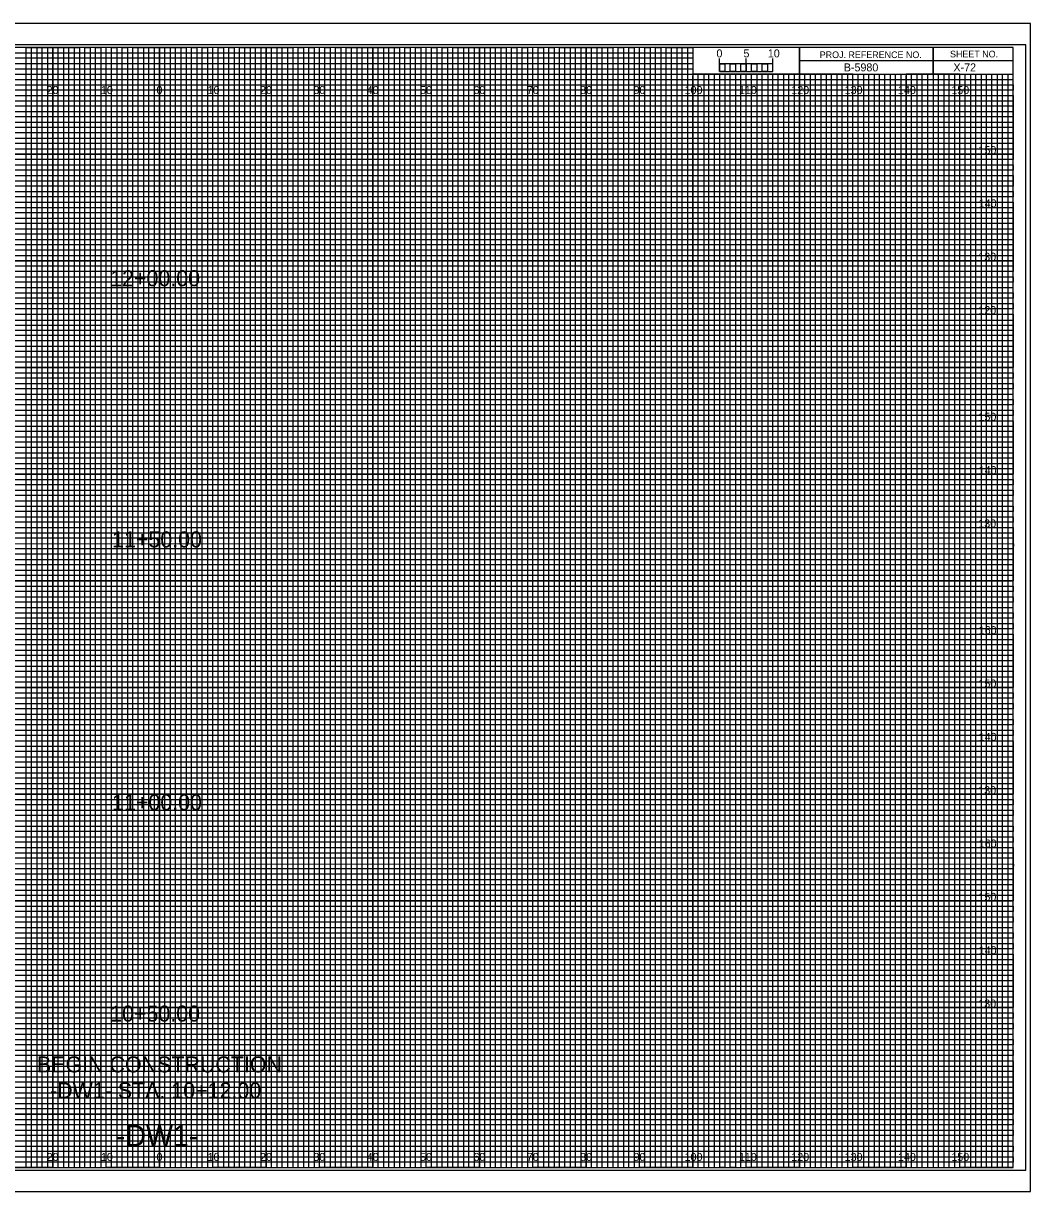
# Model space of a CAD drawing. Extents: x -13 to 323, y -5 to 434.
# Drawn here: x 134.5 to 323.3, y -4.5 to 214.5 of the extents above; entities that cross this region are included whole.
import ezdxf

# ---------------------------------------------------------------- set-up
doc = ezdxf.new("R2010")
doc.units = 0
for name, color, linetype in [('Exist Cross Section Cell', 7, 'Continuous'), ('Exist XS Center Line Elevation Label', 7, 'Continuous'), ('Exist XS Ground Line', 7, 'Continuous'), ('Prop CMT Pvmt Course 1', 7, 'Continuous'), ('Prop CMT Pvmt Course 1 Wedge', 7, 'Continuous'), ('Prop CMT Pvmt Course 2', 7, 'Continuous'), ('Prop CMT Pvmt Course 3', 7, 'Continuous'), ('Prop CMT Pvmt Surface', 7, 'Continuous'), ('Prop CMT Pvmt Surface Shoulder', 7, 'Continuous'), ('Prop CMT Shld Paved Course 1', 7, 'Continuous'), ('Prop CMT Shld Paved Course 2', 7, 'Continuous'), ('Prop CMT Shld Paved Course 3', 7, 'Continuous'), ('Prop CMT Slope Grass', 7, 'Continuous'), ('Prop CMT Subgrade Earthwork', 7, 'Continuous'), ('Prop XS Ditch Standard Text', 7, 'Continuous'), ('Prop XS SE Text', 7, 'Continuous'), ('Prop XS Side Slope Text', 7, 'Continuous')]:
    doc.layers.add(name, color=color, linetype=linetype)

msp = doc.modelspace()

# ---------------------------------------------------------------- linework, layer by layer
at = {"layer": 'Exist XS Center Line Elevation Label'}
for points in [[(125, 0), (135, 0), (135, 210), (145, 210), (145, 0), (155, 0), (155, 210), (165, 210), (165, 0), (175, 0), (175, 210), (185, 210), (185, 0), (195, 0), (195, 210), (205, 210), (205, 0), (215, 0), (215, 210), (225, 210), (225, 0), (235, 0), (235, 210), (245, 210), (245, 0), (255, 0), (255, 210), (259.93, 210), (260, 210), (260, 205), (264.99, 205), (264.99, 0), (275, 0), (275, 205), (285, 205), (285, 0), (295, 0), (295, 205), (305, 205), (305, 0), (315, 0), (315, 205)], [(0, 205), (275, 205)], [(0, 185), (320, 185), (320, 195), (0, 195)], [(0, 165), (320, 165), (320, 175), (0, 175)], [(0, 145), (320, 145), (320, 155), (0, 155)], [(0, 125), (320, 125), (320, 135), (0, 135)], [(0, 105), (320, 105), (320, 115), (0, 115)], [(0, 85), (320, 85), (320, 95), (0, 95)], [(0, 65), (320, 65), (320, 75), (0, 75)], [(0, 45), (320, 45), (320, 55), (0, 55)], [(0, 25), (320, 25), (320, 35), (0, 35)], [(0, 5), (320, 5), (320, 15), (0, 15)]]:
    msp.add_lwpolyline(points, dxfattribs=at)
at = {"layer": 'Exist XS Ground Line'}
for p, q in [((150, 210), (140, 210)), ((140, 210), (140, 0)), ((150, 0), (150, 210)), ((170, 210), (160, 210)), ((160, 210), (160, 0)), ((170, 0), (170, 210)), ((190, 210), (180, 210)), ((180, 210), (180, 0)), ((190, 0), (190, 210)), ((210, 210), (200, 210)), ((200, 210), (200, 0)), ((210, 0), (210, 210)), ((230, 210), (220, 210)), ((220, 210), (220, 0)), ((230, 0), (230, 210)), ((250, 210), (240, 210)), ((240, 210), (240, 0)), ((250, 0), (250, 210)), ((260, 210), (260, 0)), ((270, 0), (270, 205)), ((290, 205), (280, 205)), ((280, 205), (280, 0)), ((290, 0), (290, 205)), ((310, 205), (300, 205)), ((300, 205), (300, 0)), ((310, 0), (310, 205)), ((140, 0), (130, 0)), ((160, 0), (150, 0)), ((180, 0), (170, 0)), ((200, 0), (190, 0)), ((220, 0), (210, 0)), ((240, 0), (230, 0)), ((260, 0), (250, 0)), ((280, 0), (270, 0)), ((300, 0), (290, 0)), ((320, 0), (310, 0)), ((320, 0), (320, 0))]:
    msp.add_line(p, q, dxfattribs=at)
for points in [[(0, 200), (320, 200), (320, 190), (0, 190)], [(0, 180), (320, 180), (320, 170), (0, 170)], [(0, 160), (320, 160), (320, 150), (0, 150)], [(0, 140), (320, 140), (320, 130), (0, 130)], [(0, 120), (320, 120), (320, 110), (0, 110)], [(0, 100), (320, 100), (320, 90), (0, 90)], [(0, 80), (320, 80), (320, 70), (0, 70)], [(0, 60), (320, 60), (320, 50), (0, 50)], [(0, 40), (320, 40), (320, 30), (0, 30)], [(0, 20), (320, 20), (320, 10), (0, 10)]]:
    msp.add_lwpolyline(points, dxfattribs=at)
at = {"layer": 'Prop CMT Pvmt Course 2'}
for p, q in [((265, 205.49), (265, 207.9)), ((265, 206.9), (265, 207.9)), ((270, 205.49), (270, 207.9)), ((275, 205.49), (275, 207.9)), ((275, 206.9), (275, 207.9))]:
    msp.add_line(p, q, dxfattribs=at)
for points in [[(275, 206.9), (265, 206.9), (265, 205.49), (275, 205.49)], [(265, 206.9), (266, 206.9), (266, 205.49), (265, 205.49)], [(267, 206.9), (268, 206.9), (268, 205.49), (267, 205.49)], [(269, 206.9), (270, 206.9), (270, 205.49), (269, 205.49)], [(271, 206.9), (272, 206.9), (272, 205.49), (271, 205.49)], [(273, 206.9), (274, 206.9), (274, 205.49), (273, 205.49)]]:
    msp.add_lwpolyline(points, close=True, dxfattribs=at)
at = {"layer": 'Prop CMT Pvmt Course 3'}
msp.add_lwpolyline([(-13.4, -4.5), (323.3, -4.5), (323.3, 214.5), (-13.4, 214.5)], close=True, dxfattribs=at)
at = {"layer": 'Prop CMT Pvmt Surface'}
for p, q in [((140, 0), (140, 210)), ((150, 0), (150, 210)), ((160, 0), (160, 210)), ((170, 0), (170, 210)), ((180, 0), (180, 210)), ((190, 0), (190, 210)), ((200, 0), (200, 210)), ((210, 0), (210, 210)), ((220, 0), (220, 210)), ((230, 0), (230, 210)), ((240, 0), (240, 210)), ((250, 0), (250, 210)), ((260, 0), (260, 204.69)), ((270, 0), (270, 204.69)), ((280, 0), (280, 204.69)), ((290, 0), (290, 204.69)), ((300, 0), (300, 204.69)), ((310, 0), (310, 204.69)), ((0, 200), (320, 200)), ((0, 190), (320, 190)), ((0, 180), (320, 180)), ((0, 170), (320, 170)), ((0, 160), (320, 160)), ((0, 150), (320, 150)), ((0, 140), (320, 140)), ((0, 130), (320, 130)), ((0, 120), (320, 120)), ((0, 110), (320, 110)), ((0, 100), (320, 100)), ((0, 90), (320, 90)), ((0, 80), (320, 80)), ((0, 70), (320, 70)), ((0, 60), (320, 60)), ((0, 50), (320, 50)), ((0, 40), (320, 40)), ((0, 30), (320, 30)), ((0, 20), (320, 20)), ((0, 10), (320, 10))]:
    msp.add_line(p, q, dxfattribs=at)
at = {"layer": 'Prop CMT Pvmt Surface Shoulder'}
for p, q in [((323.3, 214.5), (-13.4, 214.5)), ((-13.4, -4.5), (323.3, -4.5))]:
    msp.add_line(p, q, dxfattribs=at)
at = {"layer": 'Prop CMT Shld Paved Course 1'}
for p, q in [((0, 209), (260, 209)), ((260, 209), (260, 207.98)), ((260, 207.98), (0, 207.98)), ((0, 207), (260, 207)), ((260, 205.89), (0, 205.89)), ((260, 207), (260, 205.89)), ((0, 204), (320, 204))]:
    msp.add_line(p, q, dxfattribs=at)
for points in [[(0, 203), (270, 203), (320, 203), (320, 202), (0, 202)], [(0, 201), (320, 201), (320, 199), (0, 199)], [(0, 198), (320, 198), (320, 197), (0, 196.98)], [(0, 196), (320, 196), (320, 194), (0, 194)], [(0, 193), (320, 193), (320, 192), (0, 192)], [(0, 191), (320, 191), (320, 189), (0, 189)], [(0, 188), (320, 188), (320, 187), (0, 187)], [(0, 186), (320, 186), (320, 184), (0, 184)], [(0, 183), (320, 183), (320, 182), (0, 182)], [(0, 181), (320, 181), (320, 179), (0, 179)], [(0, 178), (320, 178), (320, 177), (0, 177)], [(0, 176), (320, 176), (320, 173.95), (320, 173), (320, 172), (0, 172)], [(0, 174), (320, 174), (320, 173), (0, 173)], [(0, 171), (320, 171), (320, 169), (0, 169.03)], [(0, 169.03), (320, 169), (320, 168), (0, 168)], [(0, 167), (320, 167), (320, 166), (0, 166)], [(0, 164), (320, 164), (320, 163), (0, 163)], [(0, 162), (320, 162), (320, 161), (0, 161)], [(-0.07, 158.89), (320, 158.89), (320, 157.88), (-0.07, 157.88)], [(0, 157), (320, 157), (320, 156), (0, 156)], [(0, 154), (320, 154), (320, 153), (0, 153)], [(0, 152), (320, 152), (320, 151), (0, 151)], [(0, 149), (320, 149), (320, 148), (0, 148)], [(0, 147), (320, 147), (320, 146), (0, 146)], [(0, 144), (320, 144), (320, 143), (0, 143)], [(0, 142), (320, 142), (320, 141), (0, 141)], [(0, 139), (320, 139), (319.99, 137.98), (0, 138)], [(0, 137), (320, 137), (320, 136), (0, 136)], [(0, 134), (320, 134), (320, 133), (0, 133)], [(0, 132), (320, 132), (320, 131), (0, 131)], [(0, 129), (320, 129), (320, 128), (0, 128)], [(0, 127), (320, 127), (320, 126), (0, 126)], [(0, 124), (320, 124), (320, 123), (0, 123)], [(0, 122), (320, 122), (320, 121), (0, 121)], [(0, 119), (320, 119), (320, 118), (0, 118)], [(0, 116.99), (320.07, 116.91), (320, 116), (0, 116)], [(0, 114), (320, 114), (320, 113), (0, 113)], [(0, 112), (320, 112), (320, 111), (0, 111)], [(0, 109), (320, 109), (320, 108), (0, 108)], [(0, 107), (320, 107), (320, 106), (0, 106)], [(0, 104), (320, 104), (320, 103), (0, 103)], [(0, 102), (320, 102), (320, 101), (0, 101)], [(0, 99), (320, 99), (320, 98), (0, 98)], [(0, 97), (320, 97), (320, 96), (0, 96)], [(0, 94), (320, 94), (320, 93), (0, 93)], [(0, 92), (320, 92), (320, 91), (0, 91)], [(0, 89), (320, 89), (320, 88), (0, 88)], [(0, 87), (320, 87), (320, 86), (0, 86)], [(0, 84), (320, 84), (320, 83), (0, 83)], [(0, 82), (320, 82), (320, 81), (0, 81)], [(0, 79), (320, 79), (319.99, 77.98), (0, 78)], [(0, 77), (320, 77), (320, 76), (0, 76)], [(0, 74), (320, 74), (320, 73), (0, 73)], [(0, 72), (320, 72), (320, 71), (0, 71)], [(0, 69), (320, 69), (320, 68), (0, 68)], [(0, 67), (320, 67), (320, 66), (0, 66)], [(0, 64), (320, 64), (320, 63), (0, 63)], [(0, 62), (320, 62), (320, 61), (0, 61)], [(0, 59), (320, 59), (320, 58), (0, 58)], [(0, 56.99), (320.07, 56.91), (320, 56), (0, 56)], [(0, 54), (320, 54), (320, 53), (0, 53)], [(0, 52), (320, 52), (320, 51), (0, 51)], [(0, 49), (320, 49), (320, 48), (0, 48)], [(0, 47), (320, 47), (320, 46), (0, 46)], [(0, 44), (320, 44), (320, 43), (0, 43)], [(0, 42), (320, 42), (320, 41), (0, 41)], [(0, 39), (320, 39), (320, 38), (0, 38)], [(0, 37), (320, 37), (320, 36), (0, 36)], [(0, 34), (320, 34), (320, 33), (0, 33)], [(0, 32), (320, 32), (320, 31), (0, 31)], [(0, 29), (320, 29), (320, 28), (0, 28)], [(0, 27), (320, 27), (320, 26), (0, 26)], [(0, 24), (320, 24), (320, 23), (0, 23)], [(0, 22), (320, 22), (320, 21), (0, 21)], [(0, 19), (320, 19), (320, 18), (0, 18)], [(0, 17), (320, 17), (320, 16), (0, 16)], [(0, 14), (320, 14), (320, 13), (0, 13)], [(0, 12), (320, 12), (320, 11), (0, 11)], [(0, 9), (320, 9), (320, 8), (0, 8)], [(0, 7), (320, 7), (320, 6), (0, 6)], [(0, 4), (320, 4), (320, 3), (0, 3)], [(0, 2), (320, 2), (320, 1), (0, 1)]]:
    msp.add_lwpolyline(points, dxfattribs=at)
at = {"layer": 'Prop CMT Shld Paved Course 2'}
for p, q in [((305, 210), (305, 205)), ((305, 205), (305, 210)), ((280, 207.5), (280, 205)), ((320, 207.49), (280, 207.49)), ((280, 205), (320, 205))]:
    msp.add_line(p, q, dxfattribs=at)
for points in [[(320, 210), (0, 210), (0, 0), (320, 0)], [(280, 210), (260, 210), (260, 205.03), (280, 205.03)], [(320, 210), (280, 210), (280, 205), (320, 205)]]:
    msp.add_lwpolyline(points, close=True, dxfattribs=at)
at = {"layer": 'Prop CMT Shld Paved Course 3'}
for p, q in [((267, 205), (266.01, 205)), ((266.01, 205), (266.01, 0)), ((267, 0), (267, 205)), ((269, 205), (268, 205)), ((268, 205), (268, 0)), ((269, 0), (269, 205)), ((266.01, 0), (265, 0)), ((268, 0), (267, 0))]:
    msp.add_line(p, q, dxfattribs=at)
for points in [[(135, 0), (136, 0), (136, 210), (137, 210), (137, 0)], [(137, 0), (138, 0), (138, 210), (139, 210), (139, 0)], [(140, 0), (141, 0), (141, 210), (142, 210), (142, 0)], [(142, 0), (143, 0), (143, 210), (144, 210), (144, 0)], [(145, 0), (146, 0), (146, 210), (147, 210), (147, 0)], [(147, 0), (148, 0), (148, 210), (149, 210), (149, 0)], [(150, 0), (151, 0), (151, 210), (152, 210), (152, 0)], [(152, 0), (153, 0), (153, 210), (154, 210), (154, 0)], [(155, 0), (156, 0), (156, 210), (157, 210), (157, 0)], [(157, 0), (158, 0), (158, 210), (159, 210), (159, 0)], [(160, 0), (161, 0), (161, 210), (162, 210), (162, 0)], [(162, 0), (163, 0), (163, 210), (164, 210), (164, 0)], [(165, 0), (166, 0), (166, 210), (167, 210), (167, 0)], [(167, 0), (168, 0), (168, 210), (169, 210), (169, 0)], [(170, 0), (171, 0), (171, 210), (172, 210), (172, 0)], [(172, 0), (173, 0), (173, 210), (174, 210), (174, 0)], [(175, 0), (176, 0), (176, 210), (177, 210), (177, 0)], [(177, 0), (178, 0), (178, 210), (179, 210), (179, 0)], [(180, 0), (181, 0), (181, 210), (182, 210), (182, 0)], [(182, 0), (183, 0), (183, 210), (184, 210), (184, 0)], [(185, 0), (186, 0), (186, 210), (187, 210), (187, 0)], [(187, 0), (188, 0), (188, 210), (189, 210), (189, 0)], [(190, 0), (191, 0), (191, 210), (192, 210), (192, 0)], [(192, 0), (193, 0), (193, 210), (194, 210), (194, 0)], [(195, 0), (196, 0), (196, 210), (197, 210), (197, 0)], [(197, 0), (198, 0), (198, 210), (199, 210), (199, 0)], [(200, 0), (201, 0), (201, 210), (202, 210), (202, 0)], [(202, 0), (203, 0), (203, 210), (204, 210), (204, 0)], [(205, 0), (206, 0), (206, 210), (207, 210), (207, 0)], [(207, 0), (208, 0), (208, 210), (209, 210), (209, 0)], [(210, 0), (211, 0), (211, 210), (212, 210), (212, 0)], [(212, 0), (213, 0), (213, 210), (214, 210), (214, 0)], [(215, 0), (216, 0), (216, 210), (217, 210), (217, 0)], [(217, 0), (218, 0), (218, 210), (219, 210), (219, 0)], [(220, 0), (221, 0), (221, 210), (222, 210), (222, 0)], [(222, 0), (223, 0), (223, 210), (224, 210), (224, 0)], [(225, 0), (226, 0), (226, 210), (227, 210), (227, 0)], [(227, 0), (228, 0), (228, 210), (229, 210), (229, 0)], [(230, 0), (231, 0), (231, 210), (232, 210), (232, 0)], [(232, 0), (233, 0), (233, 210), (234, 210), (234, 0)], [(235, 0), (236, 0), (236, 210), (237, 210), (237, 0)], [(237, 0), (238, 0), (238, 210), (239, 210), (239, 0)], [(240, 0), (241, 0), (241, 210), (242, 210), (242, 0)], [(242, 0), (243, 0), (243, 210), (244, 210), (244, 0)], [(245, 0), (246, 0), (246, 210), (247, 210), (247, 0)], [(247, 0), (248, 0), (248, 210), (249, 210), (249, 0)], [(250, 0), (251, 0), (251, 210), (252, 210), (252, 0)], [(252, 0), (253, 0), (253, 210), (254, 210), (254, 0)], [(255, 0), (256, 0), (256, 210), (257, 210), (257, 0)], [(257, 0), (258, 0), (258, 210), (259, 210), (259, 0)], [(260, 0), (261, 0), (261, 205), (262.02, 205), (262.02, 0)], [(262, 0), (263, 0), (263, 205), (263.99, 205), (263.99, 0)], [(270, 0), (270.98, 0), (270.98, 205), (272, 205), (272, 0)], [(272, 0), (273, 0), (273, 205), (274.05, 205), (274.05, 0)], [(275, 0), (276, 0), (276, 205), (277, 205), (277, 0)], [(277, 0), (278, 0), (278, 205), (279, 205), (279, 0)], [(280, 0), (281, 0), (281, 205), (282, 205), (282, 0)], [(282, 0), (283, 0), (283, 205), (284, 205), (284, 0)], [(285, 0), (286, 0), (286, 205), (287, 205), (287, 0)], [(287, 0), (288, 0), (288, 205), (289, 205), (289, 0)], [(290, 0), (291, 0), (291, 205), (292, 205), (292, 0)], [(292, 0), (293, 0), (293, 205), (294, 205), (294, 0)], [(295, 0), (296, 0), (296, 205), (297, 205), (297, 0)], [(297, 0), (298, 0), (298, 205), (299, 205), (299, 0)], [(300, 0), (301, 0), (301, 205), (302, 205), (302, 0)], [(302, 0), (303, 0), (303, 205), (304, 205), (304, 0)], [(305, 0), (306, 0), (306, 205), (307, 205), (307, 0)], [(307, 0), (308, 0), (308, 205), (309, 205), (309, 0)], [(310, 0), (311, 0), (311, 205), (312, 205), (312, 0)], [(312, 0), (313, 0), (313, 205), (314, 205), (314, 0)], [(315, 0), (316, 0), (316, 205), (317, 205), (317, 0)], [(317, 0), (318, 0), (318, 205), (319, 205), (319, 0)]]:
    msp.add_lwpolyline(points, dxfattribs=at)
at = {"layer": 'Prop CMT Subgrade Earthwork'}
msp.add_lwpolyline([(-10.8, -0.5), (322.4, -0.5), (322.4, 210.5), (-10.8, 210.5)], close=True, dxfattribs=at)

# ---------------------------------------------------------------- texts
at = {"layer": 'Exist Cross Section Cell'}
for s, p in [('20', (138.86, 201.25)), ('10', (149.04, 201.25)), ('0', (159.45, 201.25)), ('0', (159.45, 201.25)), ('10', (169.04, 201.25)), ('20', (178.86, 201.25)), ('30', (188.86, 201.25)), ('40', (198.86, 201.25)), ('50', (208.86, 201.25)), ('60', (218.86, 201.25)), ('70', (228.86, 201.25)), ('80', (238.86, 201.25)), ('90', (248.86, 201.25)), ('100', (258.44, 201.25)), ('110', (268.62, 201.25)), ('120', (278.44, 201.25)), ('130', (288.44, 201.25)), ('140', (298.44, 201.25)), ('150', (308.44, 201.25)), ('20', (138.86, 1.25)), ('10', (149.04, 1.25)), ('0', (159.45, 1.25)), ('0', (159.45, 1.25)), ('10', (169.04, 1.25)), ('20', (178.86, 1.25)), ('30', (188.86, 1.25)), ('40', (198.86, 1.25)), ('50', (208.86, 1.25)), ('60', (218.86, 1.25)), ('70', (228.86, 1.25)), ('80', (238.86, 1.25)), ('90', (248.86, 1.25)), ('100', (258.44, 1.25)), ('110', (268.62, 1.25)), ('120', (278.44, 1.25)), ('130', (288.44, 1.25)), ('140', (298.44, 1.25)), ('150', (308.44, 1.25))]:
    msp.add_text(s, height=1.5, dxfattribs=at).set_placement(p)
at = {"layer": 'Prop CMT Pvmt Course 1'}
for s, p in [('150', (313.52, 190)), ('140', (313.57, 180)), ('130', (313.49, 170)), ('120', (313.5, 160)), ('150', (313.52, 140)), ('140', (313.57, 130)), ('130', (313.49, 120)), ('160', (313.57, 100)), ('150', (313.52, 90)), ('140', (313.57, 80)), ('130', (313.49, 70)), ('160', (313.57, 60)), ('150', (313.52, 50)), ('140', (313.57, 40)), ('130', (313.49, 30))]:
    msp.add_text(s, height=1.5, dxfattribs=at).set_placement(p)
at = {"layer": 'Prop CMT Pvmt Course 1 Wedge'}
for s, p in [('5', (269.47, 208.12)), ('10', (274.04, 208.12))]:
    msp.add_text(s, height=1.5, dxfattribs=at).set_placement(p)
at = {"layer": 'Prop CMT Pvmt Course 2'}
msp.add_text('0', height=1.5, dxfattribs=at).set_placement((264.41, 208.12))
at = {"layer": 'Prop CMT Shld Paved Course 2'}
for s, p in [('PROJ. REFERENCE NO.', (283.77, 207.99)), ('SHEET NO.', (308.19, 208.12))]:
    msp.add_text(s, height=1.25, dxfattribs=at).set_placement(p)
at = {"layer": 'Prop CMT Slope Grass'}
for s, p in [('12+00.00', (150.77, 165.22)), ('11+50.00', (151.13, 116.27)), ('11+00.00', (151.13, 66.98)), ('10+50.00', (150.77, 27.38)), ('BEGIN CONSTRUCTION', (137.05, 17.85)), ('-DW1- STA. 10+12.00', (139.5, 12.97))]:
    msp.add_text(s, height=3, dxfattribs=at).set_placement(p)
at = {"layer": 'Prop XS Ditch Standard Text'}
msp.add_text('-DW1-', height=4, dxfattribs=at).set_placement((151.85, 4))
at = {"layer": 'Prop XS SE Text'}
msp.add_text('X-72', height=1.5, dxfattribs=at).set_placement((308.83, 205.5))
at = {"layer": 'Prop XS Side Slope Text'}
msp.add_text('B-5980', height=1.5, dxfattribs=at).set_placement((288.28, 205.5))

doc.saveas('drawing.dxf')
